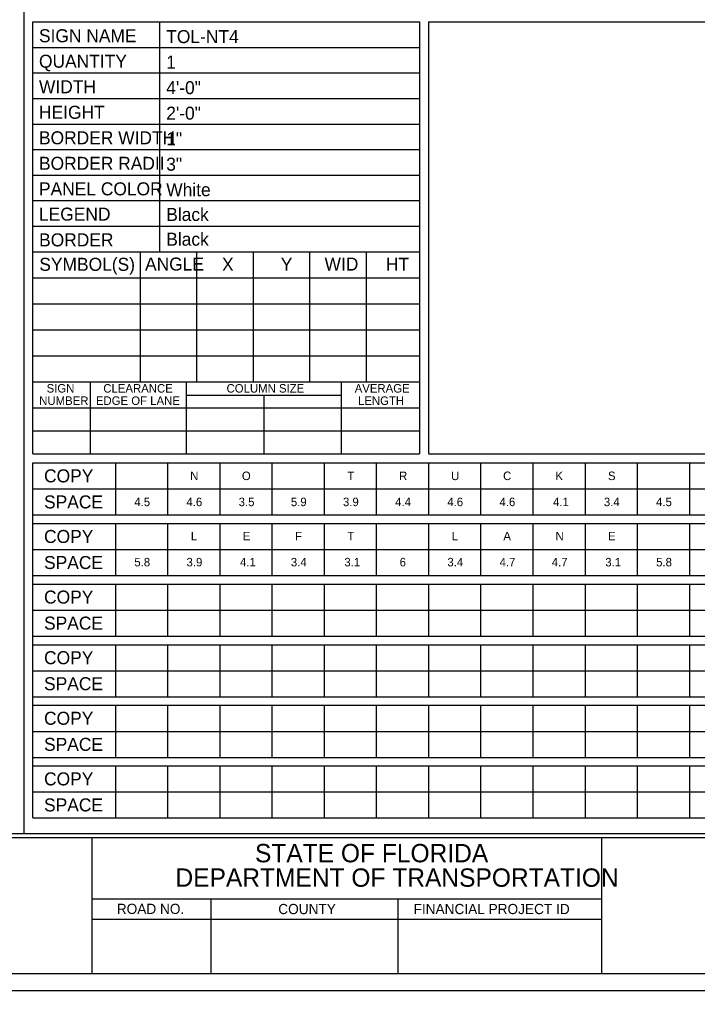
# Model space of a CAD drawing. Extents: x 17890628 to 17890844, y 17897508 to 17897992.
# Drawn here: x 17890772.14 to 17890806.91, y 17897507.74 to 17897557.55 of the extents above; entities that cross this region are included whole.
import ezdxf

# ---------------------------------------------------------------- set-up
doc = ezdxf.new("R2010")
doc.units = 0
for name, color, linetype in [('GSSign', 7, 'Continuous'), ('PlotBorder_dp', 7, 'Continuous'), ('SheetBorder_dp', 7, 'Continuous'), ('SheetLinesMisc2_dp', 7, 'Continuous'), ('TextMinor', 7, 'Continuous'), ('TextMisc', 7, 'Continuous')]:
    doc.layers.add(name, color=color, linetype=linetype)

msp = doc.modelspace()

# ---------------------------------------------------------------- linework, layer by layer
at = {"layer": 'PlotBorder_dp'}
msp.add_lwpolyline([(17890700.471, 17897507.741), (17890844.259, 17897507.741), (17890844.259, 17897600.116), (17890700.471, 17897600.116)], close=True, dxfattribs=at)
at = {"layer": 'SheetBorder_dp'}
for p, q in [((17890705.263, 17897515.585), (17890839.466, 17897515.585)), ((17890775.85, 17897515.585), (17890775.85, 17897508.613)), ((17890801.995, 17897508.612), (17890801.995, 17897515.584)), ((17890775.85, 17897512.447), (17890801.994, 17897512.447)), ((17890781.951, 17897512.447), (17890781.951, 17897508.613)), ((17890791.536, 17897512.447), (17890791.536, 17897508.613)), ((17890775.85, 17897511.401), (17890801.994, 17897511.401)), ((17890705.263, 17897508.613), (17890839.466, 17897508.613))]:
    msp.add_line(p, q, dxfattribs=at)
at = {"layer": 'SheetLinesMisc2_dp'}
for p, q in [((17890772.367, 17897599.039), (17890772.367, 17897515.791)), ((17890772.823, 17897535.261), (17890772.823, 17897557.416)), ((17890772.823, 17897557.416), (17890792.654, 17897557.416)), ((17890779.324, 17897557.416), (17890779.324, 17897545.635)), ((17890792.654, 17897557.416), (17890792.654, 17897535.261)), ((17890793.11, 17897557.416), (17890793.11, 17897535.291)), ((17890793.11, 17897557.415), (17890838.594, 17897557.415)), ((17890772.823, 17897556.108), (17890792.654, 17897556.108)), ((17890772.823, 17897554.799), (17890792.654, 17897554.799)), ((17890772.823, 17897553.49), (17890792.654, 17897553.49)), ((17890772.823, 17897552.182), (17890792.654, 17897552.182)), ((17890772.823, 17897550.873), (17890792.654, 17897550.873)), ((17890772.823, 17897549.564), (17890792.654, 17897549.564)), ((17890772.823, 17897548.256), (17890782.738, 17897548.256)), ((17890782.738, 17897548.256), (17890792.654, 17897548.256)), ((17890772.823, 17897546.947), (17890782.738, 17897546.947)), ((17890782.738, 17897546.947), (17890792.654, 17897546.947)), ((17890772.823, 17897545.635), (17890792.654, 17897545.635)), ((17890778.326, 17897545.635), (17890778.326, 17897538.954)), ((17890781.223, 17897545.635), (17890781.223, 17897538.954)), ((17890784.121, 17897545.635), (17890784.121, 17897538.954)), ((17890787.018, 17897545.635), (17890787.018, 17897538.954)), ((17890789.916, 17897545.635), (17890789.916, 17897538.954)), ((17890772.823, 17897544.299), (17890792.654, 17897544.299)), ((17890772.823, 17897542.963), (17890792.654, 17897542.963)), ((17890772.823, 17897541.627), (17890792.654, 17897541.627)), ((17890772.823, 17897540.29), (17890792.654, 17897540.29)), ((17890772.823, 17897538.954), (17890792.654, 17897538.954)), ((17890775.761, 17897538.954), (17890775.761, 17897535.261)), ((17890780.696, 17897538.954), (17890780.696, 17897535.261)), ((17890788.628, 17897538.954), (17890788.628, 17897535.261)), ((17890780.696, 17897538.274), (17890788.628, 17897538.274)), ((17890784.663, 17897538.274), (17890784.663, 17897535.261)), ((17890772.823, 17897537.635), (17890792.654, 17897537.635)), ((17890772.823, 17897536.448), (17890792.654, 17897536.448)), ((17890772.823, 17897535.261), (17890792.654, 17897535.261)), ((17890793.11, 17897535.26), (17890838.594, 17897535.26)), ((17890772.824, 17897534.804), (17890838.594, 17897534.804)), ((17890772.824, 17897516.593), (17890772.824, 17897534.804)), ((17890777.058, 17897534.804), (17890777.058, 17897532.131)), ((17890779.733, 17897534.804), (17890779.733, 17897532.131)), ((17890782.408, 17897534.804), (17890782.408, 17897532.131)), ((17890785.084, 17897534.804), (17890785.084, 17897532.131)), ((17890787.76, 17897534.804), (17890787.76, 17897532.131)), ((17890790.435, 17897534.804), (17890790.435, 17897532.131)), ((17890793.11, 17897534.804), (17890793.11, 17897532.131)), ((17890795.786, 17897534.804), (17890795.786, 17897532.131)), ((17890798.462, 17897534.804), (17890798.462, 17897532.131)), ((17890801.137, 17897534.804), (17890801.137, 17897532.131)), ((17890803.813, 17897534.804), (17890803.813, 17897532.131)), ((17890806.488, 17897534.804), (17890806.488, 17897532.131)), ((17890772.824, 17897533.468), (17890838.594, 17897533.468)), ((17890772.824, 17897532.131), (17890838.594, 17897532.131)), ((17890772.824, 17897531.696), (17890838.594, 17897531.696)), ((17890777.058, 17897531.696), (17890777.058, 17897529.023)), ((17890779.733, 17897531.696), (17890779.733, 17897529.023)), ((17890782.408, 17897531.696), (17890782.408, 17897529.023)), ((17890785.084, 17897531.696), (17890785.084, 17897529.023)), ((17890787.76, 17897531.696), (17890787.76, 17897529.023)), ((17890790.435, 17897531.696), (17890790.435, 17897529.023)), ((17890793.11, 17897531.696), (17890793.11, 17897529.023)), ((17890795.786, 17897531.696), (17890795.786, 17897529.023)), ((17890798.462, 17897531.696), (17890798.462, 17897529.023)), ((17890801.137, 17897531.696), (17890801.137, 17897529.023)), ((17890803.813, 17897531.696), (17890803.813, 17897529.023)), ((17890806.488, 17897531.696), (17890806.488, 17897529.023)), ((17890772.824, 17897530.359), (17890838.594, 17897530.359)), ((17890772.824, 17897529.023), (17890838.594, 17897529.023)), ((17890772.824, 17897528.588), (17890838.594, 17897528.588)), ((17890777.058, 17897528.588), (17890777.058, 17897525.916)), ((17890779.733, 17897528.588), (17890779.733, 17897525.916)), ((17890782.408, 17897528.588), (17890782.408, 17897525.916)), ((17890785.084, 17897528.588), (17890785.084, 17897525.916)), ((17890787.76, 17897528.588), (17890787.76, 17897525.916)), ((17890790.435, 17897528.588), (17890790.435, 17897525.916)), ((17890793.11, 17897528.588), (17890793.11, 17897525.916)), ((17890795.786, 17897528.588), (17890795.786, 17897525.916)), ((17890798.462, 17897528.588), (17890798.462, 17897525.916)), ((17890801.137, 17897528.588), (17890801.137, 17897525.916)), ((17890803.813, 17897528.588), (17890803.813, 17897525.916)), ((17890806.488, 17897528.588), (17890806.488, 17897525.916)), ((17890772.824, 17897527.252), (17890838.594, 17897527.252)), ((17890772.824, 17897525.916), (17890838.594, 17897525.916)), ((17890772.824, 17897525.48), (17890838.594, 17897525.48)), ((17890777.058, 17897525.48), (17890777.058, 17897522.808)), ((17890779.733, 17897525.48), (17890779.733, 17897522.808)), ((17890782.408, 17897525.48), (17890782.408, 17897522.808)), ((17890785.084, 17897525.48), (17890785.084, 17897522.808)), ((17890787.76, 17897525.48), (17890787.76, 17897522.808)), ((17890790.435, 17897525.48), (17890790.435, 17897522.808)), ((17890793.11, 17897525.48), (17890793.11, 17897522.808)), ((17890795.786, 17897525.48), (17890795.786, 17897522.808)), ((17890798.462, 17897525.48), (17890798.462, 17897522.808)), ((17890801.137, 17897525.48), (17890801.137, 17897522.808)), ((17890803.813, 17897525.48), (17890803.813, 17897522.808)), ((17890806.488, 17897525.48), (17890806.488, 17897522.808)), ((17890772.824, 17897524.145), (17890838.594, 17897524.145)), ((17890772.824, 17897522.808), (17890838.594, 17897522.808)), ((17890772.824, 17897522.372), (17890838.594, 17897522.372)), ((17890777.058, 17897522.372), (17890777.058, 17897519.7)), ((17890779.733, 17897522.372), (17890779.733, 17897519.7)), ((17890782.408, 17897522.372), (17890782.408, 17897519.7)), ((17890785.084, 17897522.372), (17890785.084, 17897519.7)), ((17890787.76, 17897522.372), (17890787.76, 17897519.7)), ((17890790.435, 17897522.372), (17890790.435, 17897519.7)), ((17890793.11, 17897522.372), (17890793.11, 17897519.7)), ((17890795.786, 17897522.372), (17890795.786, 17897519.7)), ((17890798.462, 17897522.372), (17890798.462, 17897519.7)), ((17890801.137, 17897522.372), (17890801.137, 17897519.7)), ((17890803.813, 17897522.372), (17890803.813, 17897519.7)), ((17890806.488, 17897522.372), (17890806.488, 17897519.7)), ((17890772.824, 17897521.036), (17890838.594, 17897521.036)), ((17890772.824, 17897519.7), (17890838.594, 17897519.7)), ((17890772.824, 17897519.264), (17890838.594, 17897519.264)), ((17890777.058, 17897519.264), (17890777.058, 17897516.593)), ((17890779.733, 17897519.264), (17890779.733, 17897516.593)), ((17890782.408, 17897519.264), (17890782.408, 17897516.593)), ((17890785.084, 17897519.264), (17890785.084, 17897516.593)), ((17890787.76, 17897519.264), (17890787.76, 17897516.593)), ((17890790.435, 17897519.264), (17890790.435, 17897516.593)), ((17890793.11, 17897519.264), (17890793.11, 17897516.593)), ((17890795.786, 17897519.264), (17890795.786, 17897516.593)), ((17890798.462, 17897519.264), (17890798.462, 17897516.593)), ((17890801.137, 17897519.264), (17890801.137, 17897516.593)), ((17890803.813, 17897519.264), (17890803.813, 17897516.593)), ((17890806.488, 17897519.264), (17890806.488, 17897516.593)), ((17890772.824, 17897517.928), (17890838.594, 17897517.928)), ((17890772.824, 17897516.593), (17890838.594, 17897516.593)), ((17890705.5, 17897515.791), (17890839.233, 17897515.791))]:
    msp.add_line(p, q, dxfattribs=at)

# ---------------------------------------------------------------- texts
at = {"layer": 'GSSign'}
for s, height, p in [('TOL-NT4', 0.6667, (17890779.667, 17897556.331)), ('1', 0.667, (17890779.667, 17897555.022)), ('4\'-0"', 0.6667, (17890779.667, 17897553.713)), ('2\'-0"', 0.6667, (17890779.667, 17897552.405)), ('1"', 0.6667, (17890779.667, 17897551.096)), ('3"', 0.6667, (17890779.667, 17897549.788)), ('White', 0.6667, (17890779.667, 17897548.479)), ('Black', 0.6667, (17890779.667, 17897547.21)), ('Black', 0.6667, (17890779.667, 17897545.941)), ('N', 0.436, (17890780.894, 17897533.921)), ('O', 0.436, (17890783.545, 17897533.921)), ('T', 0.436, (17890788.948, 17897533.921)), ('R', 0.436, (17890791.602, 17897533.921)), ('U', 0.436, (17890794.271, 17897533.921)), ('C', 0.436, (17890796.938, 17897533.921)), ('K', 0.436, (17890799.618, 17897533.921)), ('S', 0.436, (17890802.314, 17897533.921)), ('4.5', 0.4357, (17890778.029, 17897532.584)), ('4.6', 0.4357, (17890780.701, 17897532.584)), ('3.5', 0.4357, (17890783.379, 17897532.584)), ('5.9', 0.4357, (17890786.055, 17897532.584)), ('3.9', 0.4357, (17890788.729, 17897532.584)), ('4.4', 0.4357, (17890791.403, 17897532.584)), ('4.6', 0.4357, (17890794.078, 17897532.584)), ('4.6', 0.4357, (17890796.753, 17897532.584)), ('4.1', 0.4357, (17890799.496, 17897532.584)), ('3.4', 0.4357, (17890802.104, 17897532.584)), ('4.5', 0.4357, (17890804.781, 17897532.584)), ('L', 0.436, (17890780.929, 17897530.831)), ('E', 0.436, (17890783.59, 17897530.831)), ('F', 0.436, (17890786.274, 17897530.831)), ('T', 0.436, (17890788.952, 17897530.831)), ('L', 0.436, (17890794.305, 17897530.831)), ('A', 0.436, (17890796.951, 17897530.831)), ('N', 0.436, (17890799.625, 17897530.831)), ('E', 0.436, (17890802.317, 17897530.831)), ('5.8', 0.4357, (17890778.031, 17897529.495)), ('3.9', 0.4357, (17890780.707, 17897529.495)), ('4.1', 0.4357, (17890783.448, 17897529.495)), ('3.4', 0.4357, (17890786.056, 17897529.495)), ('3.1', 0.4357, (17890788.799, 17897529.495)), ('6', 0.436, (17890791.634, 17897529.495)), ('3.4', 0.4357, (17890794.082, 17897529.495)), ('4.7', 0.4357, (17890796.757, 17897529.495)), ('4.7', 0.4357, (17890799.433, 17897529.495)), ('3.1', 0.4357, (17890802.175, 17897529.495)), ('5.8', 0.4357, (17890804.784, 17897529.495))]:
    msp.add_text(s, height=height, dxfattribs=at).set_placement(p)
at = {"layer": 'TextMinor'}
for s, height, p in [('SIGN NAME', 0.6667, (17890773.142, 17897556.376)), ('QUANTITY', 0.6667, (17890773.142, 17897555.068)), ('WIDTH', 0.6667, (17890773.142, 17897553.759)), ('HEIGHT', 0.6667, (17890773.142, 17897552.45)), ('BORDER WIDTH', 0.66667, (17890773.142, 17897551.142)), ('BORDER RADII', 0.66667, (17890773.142, 17897549.833)), ('PANEL COLOR', 0.66667, (17890773.142, 17897548.524)), ('LEGEND', 0.6667, (17890773.142, 17897547.227)), ('BORDER', 0.6667, (17890773.148, 17897545.907)), ('SYMBOL(S)', 0.6667, (17890773.16, 17897544.653)), ('ANGLE', 0.6667, (17890778.58, 17897544.667)), ('X', 0.667, (17890782.527, 17897544.653)), ('Y', 0.667, (17890785.54, 17897544.653)), ('WID', 0.6667, (17890787.784, 17897544.667)), ('HT', 0.6667, (17890790.925, 17897544.654)), ('SIGN', 0.4357, (17890773.533, 17897538.41)), ('CLEARANCE', 0.4357, (17890776.44, 17897538.408)), ('COLUMN SIZE', 0.43573, (17890782.758, 17897538.408)), ('AVERAGE', 0.4357, (17890789.329, 17897538.408)), ('NUMBER', 0.4357, (17890773.154, 17897537.776)), ('EDGE OF LANE', 0.43573, (17890776.061, 17897537.776)), ('LENGTH', 0.4357, (17890789.498, 17897537.776)), ('COPY', 0.6667, (17890773.402, 17897533.805)), ('SPACE', 0.6667, (17890773.402, 17897532.468)), ('COPY', 0.6667, (17890773.402, 17897530.696)), ('SPACE', 0.6667, (17890773.402, 17897529.36)), ('COPY', 0.6667, (17890773.402, 17897527.589)), ('SPACE', 0.6667, (17890773.402, 17897526.253)), ('COPY', 0.6667, (17890773.402, 17897524.48)), ('SPACE', 0.6667, (17890773.402, 17897523.145)), ('COPY', 0.6667, (17890773.402, 17897521.372)), ('SPACE', 0.6667, (17890773.402, 17897520.036)), ('COPY', 0.6667, (17890773.402, 17897518.264)), ('SPACE', 0.6667, (17890773.402, 17897516.929))]:
    msp.add_text(s, height=height, dxfattribs=at).set_placement(p)
at = {"layer": 'TextMisc'}
for s, height, p in [('STATE OF FLORIDA', 0.94117, (17890784.217, 17897514.32)), ('DEPARTMENT OF TRANSPORTATION', 0.94117, (17890780.139, 17897513.065)), ('ROAD NO.', 0.5229, (17890777.132, 17897511.671)), ('COUNTY', 0.5229, (17890785.411, 17897511.662)), ('FINANCIAL PROJECT ID', 0.52287, (17890792.348, 17897511.662))]:
    msp.add_text(s, height=height, dxfattribs=at).set_placement(p)

doc.saveas('drawing.dxf')
